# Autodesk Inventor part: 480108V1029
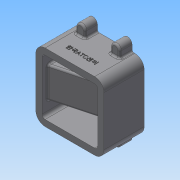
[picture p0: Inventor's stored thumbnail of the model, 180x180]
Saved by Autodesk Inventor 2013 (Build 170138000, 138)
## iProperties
Created: 2018-01
Part Number: 480108V1029
Material: 일반
Document SubType Name: Modeling
Designer: Administrator
Density: 1 g/cm^3
Author: Administrator
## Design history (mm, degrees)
sketch "스케치1"
  geometry: L1 (-40, 55)-(40, 55); L2 (55, 40)-(55, -40); L3 (40, -55)-(-40, -55); L4 (-55, -40)-(-55, 40); L5 (-55, 55)-(55, -55); L6 (55, 55)-(-55, -55); A1 r 15 centre (40, -40) between (40, -55) and (55, -40); A2 r 15 centre (-40, -40) between (-55, -40) and (-40, -55); A3 r 15 centre (-40, 40) between (-40, 55) and (-55, 40); A4 r 15 centre (40, 40) between (55, 40) and (40, 55); 1 further point
  constraints: 12 end point, 8 point on circle, 8 point on line, 8 tangent, 4 centre point, 3 equal radius, 2 midpoint, 2 parallel, 1 horizontal, 1 perpendicular
  dimensions: "d0" = 110 distance of L5.end L6.end; "d2" = 110 distance of L6.start L5.end; "d3" = 15 radius of A1
extrude "돌출1" new body sketch "스케치1" distance "d4" = 65; taper "d5" = 0 deg
sketch "스케치2"
  geometry: L1 (40, 55)-(-40, 55) reference; L2 (-55, 40)-(-55, -40) reference; L3 (55, -40)-(55, 40) reference; L4 (-45, 40)-(-45, 25); L5 (-45, 25)-(32, 25); L6 (40, 45)-(-40, 45); L7 (45, 0)-(45, 40); L8 (35, 22)-(35, 21.423); L9 (35, 21.423)-(35, 0); L10 (35, 0)-(45, 0); L11 (35, -22)-(35, -21.423); L12 (45, 0)-(45, -40); L13 (35, -21.423)-(35, 0); L14 (40, -45)-(-40, -45); L15 (-45, -25)-(32, -25); L16 (-45, -40)-(-45, -25); A1 r 15 centre (-40, 40) between (-40, 55) and (-55, 40) reference; A2 r 15 centre (40, 40) between (55, 40) and (40, 55) reference; A3 r 5 centre (-40, 40) between (-40, 45) and (-45, 40); A4 r 5 centre (40, 40) between (45, 40) and (40, 45); A5 r 3 centre (32, 22) between (35, 22) and (32, 25); A6 r 5 centre (40, -40) between (40, -45) and (45, -40); A7 r 3 centre (32, -22) between (32, -25) and (35, -22); A8 r 5 centre (-40, -40) between (-45, -40) and (-40, -45); 13 further points
  constraints: 26 end point, 16 symmetric about line, 13 point on line, 12 point on circle, 6 centre point, 6 tangent, 3 parallel, 2 horizontal alignment, 2 midpoint, 2 perpendicular, 1 coincident, 1 equal radius, 3 other
  dimensions: "d6" = 10 distance between parallel lines of L4 L2; "d7" = 10 distance between parallel lines of L6 L1; "d9" = 30 distance between parallel lines of L5 L1; "d10" = 10 distance between parallel lines of L3 L7; "d12" = 20 distance between parallel lines of L3 L8; "d13" = 5 radius of A3; "d17" = 3 radius of A5
extrude "돌출2" cut sketch "스케치2" distance "d15" = 65; taper "d16" = 0 deg
sketch "스케치3"
  geometry: L1 (40, 55)-(-40, 55) reference; L2 (-55, 40)-(-55, -40) reference; L3 (55, -40)-(55, 40) reference; L4 (-35.5, 55)-(-35.5, 65); L5 (-20.5, 65)-(-20.5, 55); L6 (-35.5, 55)-(-20.5, 55); A1 r 7.5 centre (-28, 65) between (-20.5, 65) and (-35.5, 65); 1 further point
  constraints: 6 end point, 2 point on circle, 2 point on line, 2 tangent, 1 centre point, 1 collinear, 1 parallel, 1 perpendicular
  dimensions: "d18" = 10 distance from line of A1.centre L1; "d19" = 7.5 radius of A1; "d20" = 27 distance from line of A1.centre L2
extrude "돌출3" join sketch "스케치3" distance "d21" = 20; taper "d22" = 0 deg
hole "구멍1" diameter "d25" = 3.242; stored, may be unused: countersink angle "d29" = 90 deg, drill point angle "d31" = 118 deg; dims "d26" = 9, "d27" = 4, "d28" = 2, "d30" = 11, "d32" = 10, "d33" = 10
sketch "스케치5"
  geometry: L1 (55, -40)-(55, 40) reference; L2 (-55, 7.5)-(-36, 7.5); L3 (-36, 7.5)-(-36, 16); L4 (-36, 16)-(-22, 16); L5 (-22, 16)-(-22, 20); L6 (-22, 20)-(25, 20); L7 (25, 20)-(25, 15); L8 (25, 15)-(30, 15); L9 (30, 15)-(30, 0); L10 (30, 0)-(-55, 0); L11 (-55, 0)-(-55, 7.5); L12 (-55, -40)-(-55, 40) reference; 1 further point
  constraints: 20 end point, 6 parallel, 3 perpendicular, 1 collinear, 1 point on line
  dimensions: "d34" = 15 diameter of L2 L10; "d35" = 19 distance of L2.start L2.end; "d36" = 14 distance of L3.end L4.end; "d37" = 47 distance of L5.end L6.end; "d38" = 5 distance of L7.end L8.end; "d39" = 32 diameter of L4 L10; "d40" = 40 diameter of L6 L10; "d41" = 30 diameter of L8 L10
revolve "회전1" sketch "스케치5" stored, may be unused: angle "d42" = 90 deg
sketch "스케치7"
  geometry: L1 (-55, 0)-(-55, 65) reference; L2 (45, 65)-(45, 0) reference; L3 (35, 65)-(35, 0) reference; L4 (45, 0)-(45, 30); L5 (-45, 0)-(45, 0); L6 (-45, 8.564)-(-45, 0); L7 (45, 30)-(35, 30); L8 (-55, 0)-(-40, 0) reference; L9 (-45, 0)-(32, 0) reference; L10 (-45, 8.564)-(35, 30); 1 further point
  constraints: 10 end point, 2 collinear, 2 perpendicular, 2 point on line
  dimensions: "d48" = 30 distance between parallel lines of L7 L5; "d50" = 105 deg angle of L10 L6; "d52" = 10 distance between parallel lines of L6 L1
extrude "돌출4" cut sketch "스케치7" stored distance "d45" = 60; taper "d46" = 0 deg
sketch "스케치8"
  geometry: L1 (-55, 29.061)-(-17, 39.243); L2 (-17, 39.243)-(-17, 45); L3 (-17, 45)-(20, 45); L4 (20, 45)-(20, 31.157); L5 (20, 31.157)-(-55, 11.061); L6 (-55, 11.061)-(-55, 29.061); L7 (32, 29.196)-(-45, 8.564) reference; L8 (-55, 0)-(-55, 65) reference; L9 (25, 65)-(25, 45) reference; L10 (-22, 65)-(-22, 49) reference; L11 (-22, 65)-(25, 65) reference; L12 (32, 29.196)-(-45, 8.564) reference; L13 (-45, 65)-(-45, 8.564) reference; L14 (32, 65)-(-45, 65) reference; L15 (32, 65)-(32, 29.196) reference; L16 (25, 45)-(-22, 45) reference; 2 further points
  constraints: 12 end point, 2 collinear, 2 parallel, 2 perpendicular, 1 vertical
  dimensions: "d53" = 5 distance between parallel lines of L7 L5; "d56" = 5 distance between parallel lines of L4 L9; "d57" = 5 distance between parallel lines of L2 L10 (derived); "d58" = 75 deg angle of L1 L8; "d59" = 37 distance between parallel lines of L4 L2; "d60" = 18 distance of L5.end L1.start
extrude "돌출5" cut sketch "스케치8" stored distance "d62" = 30; taper "d63" = 0 deg
fillet "모깎기1" dims "d65" = 1
fillet "모깎기2" dims "d66" = 3
fillet "모깎기3" dims "d67" = 3
fillet "모깎기4" dims "d68" = 3
fillet "모깎기5" dims "d69" = 3
fillet "모깎기6" dims "d70" = 3
fillet "모깎기10" dims "d74" = 3
fillet "모깎기11" dims "d75" = 3
sketch "스케치13"
  geometry: L1 (-17, 15)-(20, 15); L2 (20, 15)-(20, -15); L3 (20, -15)-(-17, -15); L4 (-17, -15)-(-17, 15); L5 (-22, 16)-(-22, -16) reference; L6 (25, 15)-(25, -15) reference; 2 further points
  constraints: 8 end point, 2 parallel, 1 horizontal, 1 horizontal alignment, 1 midpoint, 1 perpendicular
  dimensions: "d77" = 5 distance between parallel lines of L4 L5; "d78" = 5 distance between parallel lines of L2 L6; "d79" = 30 distance between parallel lines of L1 L3
extrude "돌출6" cut sketch "스케치13" distance "d80" = 30; taper "d81" = 0 deg
sketch "스케치14"
  geometry: L1 (-36, -7.5)-(-55, -7.5) reference; L2 (-55, -7.5)-(-55, -40) reference; L3 (-40, -55)-(-38.5, -55) reference; L4 (-35.5, -65)-(-35.5, -58) reference; L5 (-20.5, -58)-(-20.5, -65) reference; L6 (-17.5, -55)-(17.5, -55) reference; L7 (20.5, -58)-(20.5, -65) reference; L8 (35.5, -65)-(35.5, -58) reference; L9 (38.5, -55)-(40, -55) reference; L10 (55, -40)-(55, 40) reference; L11 (40, 55)-(38.5, 55) reference; L12 (35.5, 65)-(35.5, 58) reference; L13 (20.5, 58)-(20.5, 65) reference; L14 (17.5, 55)-(-17.5, 55) reference; L15 (-20.5, 58)-(-20.5, 65) reference; L16 (-35.5, 65)-(-35.5, 58) reference; L17 (-38.5, 55)-(-40, 55) reference; L18 (-55, 40)-(-55, 7.5) reference; L19 (-55, 7.5)-(-36, 7.5) reference; L20 (-36, 7.5)-(-36, 15) reference; L21 (-35, 16)-(-22, 16) reference; L22 (-22, 16)-(-22, 19) reference; L23 (-21, 20)-(24, 20) reference; L24 (25, 19)-(25, 15) reference; L25 (25, 15)-(29, 15) reference; L26 (30, 14)-(30, -14) reference; L27 (29, -15)-(25, -15) reference; L28 (25, -15)-(25, -19) reference; L29 (24, -20)-(-21, -20) reference; L30 (-22, -19)-(-22, -16) reference; L31 (-22, -16)-(-35, -16) reference; L32 (-36, -15)-(-36, -7.5) reference; L33 (35, -22)-(35, 22) reference; L34 (32, 25)-(-42, 25) reference; L35 (-45, 28)-(-45, 40) reference; L36 (-40, 45)-(40, 45) reference; L37 (45, 40)-(45, -40) reference; L38 (40, -45)-(-40, -45) reference; L39 (-45, -40)-(-45, -28) reference; L40 (-42, -25)-(32, -25) reference; C1 r 1.621 at (28, -65) reference; C2 r 1.621 at (-28, -65) reference; C3 r 1.621 at (28, 65) reference; C4 r 1.621 at (-28, 65) reference; A1 r 15 centre (-40, -40) between (-55, -40) and (-40, -55) reference; A2 r 3 centre (-38.5, -58) between (-35.5, -58) and (-38.5, -55) reference; A3 r 7.5 centre (-28, -65) between (-35.5, -65) and (-20.5, -65) reference; A4 r 3 centre (-17.5, -58) between (-17.5, -55) and (-20.5, -58) reference; A5 r 3 centre (17.5, -58) between (20.5, -58) and (17.5, -55) reference; A6 r 7.5 centre (28, -65) between (20.5, -65) and (35.5, -65) reference; A7 r 3 centre (38.5, -58) between (38.5, -55) and (35.5, -58) reference; A8 r 15 centre (40, -40) between (40, -55) and (55, -40) reference; A9 r 15 centre (40, 40) between (55, 40) and (40, 55) reference; A10 r 3 centre (38.5, 58) between (35.5, 58) and (38.5, 55) reference; A11 r 7.5 centre (28, 65) between (35.5, 65) and (20.5, 65) reference; A12 r 3 centre (17.5, 58) between (17.5, 55) and (20.5, 58) reference; A13 r 3 centre (-17.5, 58) between (-20.5, 58) and (-17.5, 55) reference; A14 r 7.5 centre (-28, 65) between (-20.5, 65) and (-35.5, 65) reference; A15 r 3 centre (-38.5, 58) between (-38.5, 55) and (-35.5, 58) reference; A16 r 15 centre (-40, 40) between (-40, 55) and (-55, 40) reference; A17 r 1 centre (-35, 15) between (-35, 16) and (-36, 15) reference; A18 r 1 centre (-21, 19) between (-21, 20) and (-22, 19) reference; A19 r 1 centre (24, 19) between (25, 19) and (24, 20) reference; A20 r 1 centre (29, 14) between (30, 14) and (29, 15) reference; A21 r 1 centre (29, -14) between (29, -15) and (30, -14) reference; A22 r 1 centre (24, -19) between (24, -20) and (25, -19) reference; A23 r 1 centre (-21, -19) between (-22, -19) and (-21, -20) reference; A24 r 1 centre (-35, -15) between (-36, -15) and (-35, -16) reference; A25 r 3 centre (32, 22) between (35, 22) and (32, 25) reference; A26 r 3 centre (-42, 28) between (-45, 28) and (-42, 25) reference; A27 r 5 centre (-40, 40) between (-40, 45) and (-45, 40) reference; A28 r 5 centre (40, 40) between (45, 40) and (40, 45) reference; A29 r 5 centre (40, -40) between (40, -45) and (45, -40) reference; A30 r 5 centre (-40, -40) between (-45, -40) and (-40, -45) reference; A31 r 3 centre (-42, -28) between (-42, -25) and (-45, -28) reference; A32 r 3 centre (32, -22) between (32, -25) and (35, -22) reference; 1 further point
fillet "모깎기12" dims "d82" = 3
chamfer "모따기1" distance "d83" = 1; stored, may be unused: second distance "d84" = 2, angle "d85" = 45 deg
chamfer "모따기2" distance "d86" = 1; stored, may be unused: second distance "d87" = 2, angle "d88" = 45 deg
fillet "모깎기13" dims "d89" = 3
node "작업 평면1"
sketch "스케치18"
  geometry: L1 (-55, 0)-(-55, 65) reference; L2 (40, 0)-(-40, 0) reference; 2 further points
  constraints: 1 other
  dimensions: "d93" = 55 distance from line of point (0, 20) L1; "d94" = 20 distance from line of point (0, 20) L2
fillet "모깎기14" dims "d95" = 3
fillet "모깎기15" dims "d96" = 3
feature "엠보싱1" dims "d0" = 110, "d2" = 110, "d3" = 15, "d97" = 0.5, "d98" = 0
node "솔리드1"
mirror "대칭2"
mirror "대칭3"
node "투영된 루프1"
